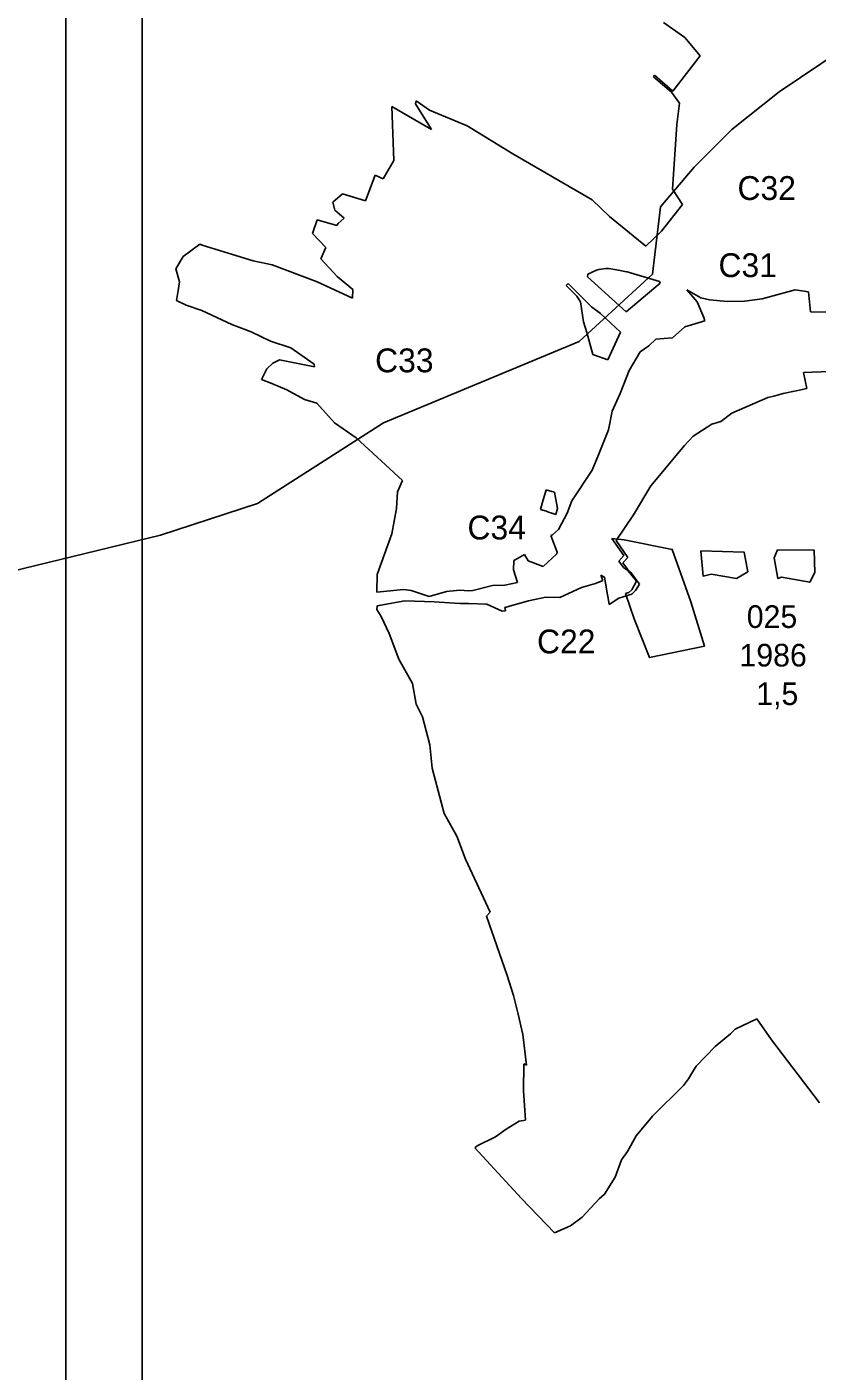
# Model space of a CAD drawing. Extents: x -557103 to -548162, y -1041918 to -1033974.
# Drawn here: x -555357 to -554362, y -1039045 to -1037353 of the extents above; entities that cross this region are included whole.
import ezdxf

# ---------------------------------------------------------------- set-up
doc = ezdxf.new("R2010")
doc.units = 0
for name, color, linetype in [('body1', 7, 'Continuous'), ('body3', 7, 'Continuous'), ('Rámeček', 7, 'Continuous'), ('Vrstva 16', 7, 'Continuous'), ('Vrstva 37', 7, 'Continuous'), ('Vrstva 9', 7, 'Continuous')]:
    doc.layers.add(name, color=color, linetype=linetype)

msp = doc.modelspace()

# ---------------------------------------------------------------- linework, layer by layer
at = {"layer": 'body1'}
msp.add_lwpolyline([(-550469.3, -1040018.6), (-555211.6, -1040018.6), (-555211.6, -1034654.7), (-550469.3, -1034654.7)], close=True, dxfattribs=at)
at = {"layer": 'body3'}
for p, q in [((-554555.1, -1037348), (-554528.3, -1037366.9)), ((-554528.3, -1037366.9), (-554509.2, -1037390)), ((-554509.2, -1037390), (-554543.6, -1037434.2)), ((-554566.4, -1037414.3), (-554567.7, -1037416.2)), ((-554543.6, -1037434.2), (-554566.4, -1037414.3)), ((-554567.7, -1037416.2), (-554545, -1037435.7)), ((-554866.5, -1037446.5), (-554867.6, -1037450.3)), ((-554849.7, -1037458.1), (-554866.5, -1037446.5)), ((-554545, -1037435.7), (-554534.9, -1037449.4)), ((-554847.4, -1037482.8), (-554897.1, -1037453.8)), ((-554897.1, -1037453.8), (-554894.8, -1037521.6)), ((-554867.6, -1037450.3), (-554847.4, -1037482.8)), ((-554802.2, -1037478), (-554849.7, -1037458.1)), ((-554534.9, -1037449.4), (-554538.3, -1037476.5)), ((-554744.8, -1037513.3), (-554802.2, -1037478)), ((-554538.3, -1037476.5), (-554544, -1037557.7)), ((-554644.8, -1037571.1), (-554744.8, -1037513.3)), ((-554894.8, -1037521.6), (-554908.1, -1037544.8)), ((-554918.2, -1037539.9), (-554930.4, -1037572.5)), ((-554908.1, -1037544.8), (-554918.2, -1037539.9)), ((-554959.2, -1037563.4), (-554971.7, -1037573.9)), ((-554930.4, -1037572.5), (-554959.2, -1037563.4)), ((-554544, -1037557.7), (-554531.3, -1037576.9)), ((-554971.7, -1037573.9), (-554968.9, -1037584.2)), ((-554968.9, -1037584.2), (-554957.3, -1037594)), ((-554623.2, -1037591.9), (-554644.8, -1037571.1)), ((-554531.3, -1037576.9), (-554557.8, -1037610.7)), ((-554991.2, -1037596.1), (-554997.1, -1037613.4)), ((-554966.6, -1037603.5), (-554991.2, -1037596.1)), ((-554965, -1037600.9), (-554966.6, -1037603.5)), ((-554957.3, -1037594), (-554965, -1037600.9)), ((-554577.2, -1037629.5), (-554623.2, -1037591.9)), ((-554997.1, -1037613.4), (-554980.4, -1037631.2)), ((-554557.8, -1037610.7), (-554577.2, -1037629.5)), ((-555139.1, -1037627), (-555160, -1037642.6)), ((-555135.9, -1037628.2), (-555139.1, -1037627)), ((-555097.7, -1037639.9), (-555135.9, -1037628.2)), ((-554980.4, -1037631.2), (-554986.6, -1037645.4)), ((-555160, -1037642.6), (-555169.1, -1037658.1)), ((-555071.7, -1037647.8), (-555097.7, -1037639.9)), ((-555048, -1037652.9), (-555071.7, -1037647.8)), ((-554986.6, -1037645.4), (-554965.9, -1037667.7)), ((-555169.1, -1037658.1), (-555164.8, -1037674.5)), ((-554991.4, -1037674.5), (-555048, -1037652.9)), ((-554965.9, -1037667.7), (-554946.2, -1037684.1)), ((-554650.8, -1037668), (-554650.3, -1037664.8)), ((-554602.3, -1037712.2), (-554650.8, -1037668)), ((-554650.3, -1037664.8), (-554639.5, -1037659.6)), ((-554639.5, -1037659.6), (-554636.6, -1037658.8)), ((-554636.6, -1037658.8), (-554630.6, -1037658)), ((-554630.6, -1037658), (-554627.6, -1037657.7)), ((-554627.6, -1037657.7), (-554624.6, -1037657.7)), ((-554624.6, -1037657.7), (-554621.6, -1037658)), ((-554621.6, -1037658), (-554609.9, -1037660)), ((-554609.9, -1037660), (-554604, -1037661.2)), ((-554604, -1037661.2), (-554601.1, -1037661.9)), ((-554601.1, -1037661.9), (-554560.2, -1037673.8)), ((-555166.5, -1037685.3), (-555168.5, -1037697.7)), ((-555164.8, -1037674.5), (-555166.5, -1037685.3)), ((-554946.7, -1037695), (-554991.4, -1037674.5)), ((-554946.2, -1037684.1), (-554946.7, -1037695)), ((-554677.7, -1037679.1), (-554675.1, -1037676.6)), ((-554664.3, -1037692.3), (-554677.7, -1037679.1)), ((-554675.1, -1037676.6), (-554645.9, -1037705.7)), ((-554559.4, -1037676), (-554602.3, -1037712.2)), ((-554560.2, -1037673.8), (-554559.4, -1037676)), ((-554512.9, -1037699.5), (-554525.9, -1037684.5)), ((-554525.9, -1037684.5), (-554508, -1037694.3)), ((-554430.8, -1037695.6), (-554389.5, -1037684.6)), ((-554389.5, -1037684.6), (-554372.6, -1037686.9)), ((-555168.5, -1037697.7), (-555156.2, -1037703.5)), ((-554659.6, -1037699.7), (-554664.3, -1037692.3)), ((-554655.8, -1037724.7), (-554659.6, -1037699.7)), ((-554504.2, -1037719.4), (-554512.9, -1037699.5)), ((-554508, -1037694.3), (-554497.1, -1037697.1)), ((-554497.1, -1037697.1), (-554474.7, -1037698.9)), ((-554474.7, -1037698.9), (-554453.1, -1037698.6)), ((-554453.1, -1037698.6), (-554430.8, -1037695.6)), ((-554372.6, -1037686.9), (-554370.2, -1037712)), ((-555156.2, -1037703.5), (-555136.7, -1037710.3)), ((-555136.7, -1037710.3), (-555098.7, -1037728.2)), ((-554645.9, -1037705.7), (-554634.3, -1037714.3)), ((-554634.3, -1037714.3), (-554609.3, -1037737.7)), ((-554503.1, -1037723.3), (-554504.2, -1037719.4)), ((-554370.2, -1037712), (-554337.8, -1037712.6)), ((-555098.7, -1037728.2), (-555074.2, -1037737.2)), ((-554651.9, -1037738.1), (-554655.8, -1037724.7)), ((-554543.7, -1037744.9), (-554528.2, -1037731)), ((-554528.2, -1037731), (-554503.1, -1037723.3)), ((-555074.2, -1037737.2), (-555049.9, -1037749)), ((-555049.9, -1037749), (-555024.6, -1037757.5)), ((-554644.1, -1037765.9), (-554651.9, -1037738.1)), ((-554609.3, -1037737.7), (-554625.3, -1037772.6)), ((-554573.6, -1037754.8), (-554564.8, -1037746.7)), ((-554564.8, -1037746.7), (-554543.7, -1037744.9)), ((-555024.6, -1037757.5), (-554995, -1037777.8)), ((-554625.3, -1037772.6), (-554644.1, -1037765.9)), ((-554598.4, -1037785.9), (-554584.7, -1037762.4)), ((-554584.7, -1037762.4), (-554573.6, -1037754.8)), ((-555054.8, -1037784), (-555061.2, -1037797.1)), ((-555047.3, -1037776.8), (-555054.8, -1037784)), ((-555038.9, -1037772.7), (-555047.3, -1037776.8)), ((-554994.8, -1037781.5), (-555038.9, -1037772.7)), ((-554995, -1037777.8), (-554994.8, -1037781.5)), ((-554609.6, -1037814.8), (-554598.4, -1037785.9)), ((-554304.4, -1037785.4), (-554378.9, -1037788.6)), ((-555061.2, -1037797.1), (-555048.4, -1037802.2)), ((-555048.4, -1037802.2), (-555029.6, -1037810.2)), ((-554378.9, -1037788.6), (-554374.6, -1037808.6)), ((-555029.6, -1037810.2), (-555007.4, -1037822.3)), ((-554619.8, -1037837.3), (-554609.6, -1037814.8)), ((-554423.7, -1037820), (-554469.3, -1037839.7)), ((-554416.4, -1037818.2), (-554423.7, -1037820)), ((-554404.3, -1037814.7), (-554416.4, -1037818.2)), ((-554388, -1037811.4), (-554404.3, -1037814.7)), ((-554374.6, -1037808.6), (-554388, -1037811.4)), ((-555007.4, -1037822.3), (-554991.6, -1037827.2)), ((-554991.6, -1037827.2), (-554969.3, -1037851.7)), ((-554624.6, -1037860.5), (-554619.8, -1037837.3)), ((-554969.3, -1037851.7), (-554942.1, -1037870.8)), ((-554494.1, -1037853.3), (-554517.6, -1037868.8)), ((-554482.9, -1037850.1), (-554494.1, -1037853.3)), ((-554469.3, -1037839.7), (-554482.9, -1037850.1)), ((-554942.1, -1037870.8), (-554884, -1037924.3)), ((-554637.2, -1037892.1), (-554624.6, -1037860.5)), ((-554517.6, -1037868.8), (-554528.7, -1037880.3)), ((-554528.7, -1037880.3), (-554571.2, -1037931.2)), ((-554644.8, -1037911.5), (-554637.2, -1037892.1)), ((-554670.6, -1037950.1), (-554644.8, -1037911.5)), ((-554890.2, -1037938.6), (-554891.4, -1037959.7)), ((-554884, -1037924.3), (-554890.2, -1037938.6)), ((-554707.5, -1037951.8), (-554702.7, -1037936.1)), ((-554702.7, -1037936.1), (-554695.8, -1037938.3)), ((-554695.8, -1037938.3), (-554692.4, -1037939.2)), ((-554692.4, -1037939.2), (-554688.5, -1037959.8)), ((-554571.2, -1037931.2), (-554593, -1037967.8)), ((-554710.2, -1037960.8), (-554707.5, -1037951.8)), ((-554676.6, -1037965.6), (-554670.6, -1037950.1)), ((-554891.4, -1037959.7), (-554897.3, -1037991.4)), ((-554702.6, -1037963.2), (-554710.2, -1037960.8)), ((-554700, -1037964.1), (-554702.6, -1037963.2)), ((-554697.1, -1037965), (-554700, -1037964.1)), ((-554690.8, -1037967), (-554697.1, -1037965)), ((-554688.5, -1037959.8), (-554690.8, -1037967)), ((-554687.3, -1037986.2), (-554676.6, -1037965.6)), ((-554593, -1037967.8), (-554614.9, -1038000)), ((-554695.1, -1037992.7), (-554687.3, -1037986.2)), ((-554897.3, -1037991.4), (-554915.7, -1038042.6)), ((-554696.9, -1037993.8), (-554695.1, -1037992.7)), ((-554688.9, -1038014.6), (-554696.9, -1037993.8)), ((-554614.9, -1038000), (-554599.9, -1038021.3)), ((-554743.6, -1038025.1), (-554741.9, -1038024.1)), ((-554741.9, -1038024.1), (-554730.1, -1038017.5)), ((-554730.1, -1038017.5), (-554725.6, -1038025.6)), ((-554706.8, -1038032.8), (-554689.3, -1038016.6)), ((-554689.3, -1038016.6), (-554688.9, -1038014.6)), ((-554599.9, -1038021.3), (-554606.3, -1038028.1)), ((-554744.2, -1038036.9), (-554743.6, -1038025.1)), ((-554739, -1038052.6), (-554744.2, -1038036.9)), ((-554725.6, -1038025.6), (-554706.8, -1038032.8)), ((-554606.3, -1038028.1), (-554600.7, -1038036.2)), ((-554600.7, -1038036.2), (-554596.2, -1038040)), ((-554596.2, -1038040), (-554594.6, -1038042.1)), ((-554915.7, -1038042.6), (-554916.3, -1038065.1)), ((-554795.4, -1038062.8), (-554770.6, -1038056.5)), ((-554770.6, -1038056.5), (-554754.9, -1038056.3)), ((-554754.9, -1038056.3), (-554739, -1038052.6)), ((-554640.6, -1038053.9), (-554658.5, -1038059.1)), ((-554631.6, -1038050.2), (-554640.6, -1038053.9)), ((-554629.4, -1038045.9), (-554634, -1038043.7)), ((-554634, -1038043.7), (-554631.6, -1038050.2)), ((-554627.4, -1038058.3), (-554629.4, -1038045.9)), ((-554594.6, -1038042.1), (-554589.1, -1038049.7)), ((-554585.3, -1038054.8), (-554590.3, -1038062.8)), ((-554589.1, -1038049.7), (-554585.3, -1038054.8)), ((-554916.3, -1038065.1), (-554882.6, -1038061.4)), ((-554882.6, -1038061.4), (-554873.1, -1038062.8)), ((-554873.1, -1038062.8), (-554850.2, -1038070.5)), ((-554850.2, -1038070.5), (-554828.3, -1038064.3)), ((-554828.3, -1038064.3), (-554811.7, -1038062.4)), ((-554811.7, -1038062.4), (-554800.8, -1038063.2)), ((-554800.8, -1038063.2), (-554795.4, -1038062.8)), ((-554703.4, -1038071.1), (-554725.1, -1038076)), ((-554685.7, -1038071.8), (-554703.4, -1038071.1)), ((-554658.5, -1038059.1), (-554685.7, -1038071.8)), ((-554626.4, -1038063.7), (-554627.4, -1038058.3)), ((-554624.6, -1038075.1), (-554626.4, -1038063.7)), ((-554611.6, -1038072.3), (-554623.7, -1038080.3)), ((-554595, -1038067.6), (-554611.6, -1038072.3)), ((-554590.3, -1038062.8), (-554595, -1038067.6)), ((-554915.7, -1038082.3), (-554916.3, -1038086.7)), ((-554916.3, -1038086.7), (-554910.5, -1038095.6)), ((-554880.8, -1038075.8), (-554915.7, -1038082.3)), ((-554843.8, -1038077), (-554880.8, -1038075.8)), ((-554811.6, -1038079), (-554843.8, -1038077)), ((-554806.4, -1038079.2), (-554811.6, -1038079)), ((-554800.5, -1038079.4), (-554806.4, -1038079.2)), ((-554777.6, -1038080.2), (-554800.5, -1038079.4)), ((-554758.4, -1038089), (-554777.6, -1038080.2)), ((-554754.2, -1038088.3), (-554758.4, -1038089)), ((-554725.1, -1038076), (-554755, -1038084.3)), ((-554755, -1038084.3), (-554754.2, -1038088.3)), ((-554623.7, -1038080.3), (-554624.6, -1038075.1)), ((-554910.5, -1038095.6), (-554900.7, -1038117.1)), ((-554900.7, -1038117.1), (-554888.6, -1038149.1)), ((-554888.6, -1038149.1), (-554871.2, -1038179.8)), ((-554871.2, -1038179.8), (-554866.4, -1038206)), ((-554866.4, -1038206), (-554858.5, -1038221.9)), ((-554858.5, -1038221.9), (-554849.5, -1038257)), ((-554849.5, -1038257), (-554846.3, -1038286.5)), ((-554846.3, -1038286.5), (-554831.2, -1038343.4)), ((-554831.2, -1038343.4), (-554815.2, -1038371.9)), ((-554815.2, -1038371.9), (-554804.6, -1038401.1)), ((-554804.6, -1038401.1), (-554773.3, -1038467.9)), ((-554773.3, -1038467.9), (-554778.1, -1038472.8)), ((-554778.1, -1038472.8), (-554752.2, -1038547.4)), ((-554752.2, -1038547.4), (-554744.2, -1038572.4)), ((-554744.2, -1038572.4), (-554738.1, -1038595.9)), ((-554738.1, -1038595.9), (-554732.1, -1038621.7)), ((-554471, -1038620.8), (-554464.8, -1038615.1)), ((-554464.8, -1038615.1), (-554437.8, -1038602)), ((-554437.8, -1038602), (-554419.3, -1038628.4)), ((-554732.1, -1038621.7), (-554727.7, -1038660.3)), ((-554489.9, -1038636.9), (-554471, -1038620.8)), ((-554419.3, -1038628.4), (-554358.8, -1038707.9)), ((-554514.1, -1038661.6), (-554489.9, -1038636.9)), ((-554731.1, -1038658.8), (-554731.5, -1038692.4)), ((-554727.7, -1038660.3), (-554731.1, -1038658.8)), ((-554520.8, -1038672.6), (-554514.1, -1038661.6)), ((-554529.8, -1038685.8), (-554523.8, -1038677.6)), ((-554523.8, -1038677.6), (-554520.8, -1038672.6)), ((-554731.5, -1038692.4), (-554728.9, -1038729.5)), ((-554569.2, -1038724.6), (-554529.8, -1038685.8)), ((-554736.7, -1038730.9), (-554753.4, -1038740.8)), ((-554728.9, -1038729.5), (-554736.7, -1038730.9)), ((-554589.6, -1038749.4), (-554569.2, -1038724.6)), ((-554766.8, -1038750.5), (-554789.8, -1038762)), ((-554753.4, -1038740.8), (-554766.8, -1038750.5)), ((-554600.6, -1038768.9), (-554589.6, -1038749.4)), ((-554789.8, -1038762), (-554792.9, -1038764.4)), ((-554792.9, -1038764.4), (-554733.8, -1038828.1)), ((-554616, -1038801.2), (-554608.2, -1038779.5)), ((-554608.2, -1038779.5), (-554600.6, -1038768.9)), ((-554629.6, -1038822.5), (-554616, -1038801.2)), ((-554733.8, -1038828.1), (-554692.4, -1038871.2)), ((-554657.4, -1038851.4), (-554636.1, -1038828.4)), ((-554636.1, -1038828.4), (-554629.6, -1038822.5)), ((-554672.3, -1038862.7), (-554657.4, -1038851.4)), ((-554692.4, -1038871.2), (-554672.3, -1038862.7))]:
    msp.add_line(p, q, dxfattribs=at)
at = {"layer": 'Rámeček'}
for points in [[(-555307.9, -1039662.1), (-550042, -1039662.1), (-550042, -1034604.4), (-555307.9, -1034604.4)], [(-555307.9, -1034604.4), (-548161.9, -1034604.4), (-548161.9, -1039661.8), (-555307.9, -1039661.8)]]:
    msp.add_lwpolyline(points, close=True, dxfattribs=at)
at = {"layer": 'Vrstva 16'}
msp.add_lwpolyline([(-554172.9, -1037275.9), (-554409.6, -1037435.4), (-554469.3, -1037482.8), (-554516.7, -1037530.1), (-554559, -1037580), (-554569, -1037664.7), (-554661.2, -1037749.5), (-554907.8, -1037851.7), (-555066.3, -1037953.4), (-555188.4, -1037993.2), (-555425.1, -1038050.6)], dxfattribs=at)
at = {"layer": 'Vrstva 9'}
msp.add_line((-554604.8, -1037999.2), (-554620.2, -1037997.6), dxfattribs=at)
msp.add_lwpolyline([(-554620.2, -1037997.6), (-554605.2, -1038019), (-554611.2, -1038026.1), (-554605.5, -1038033.9), (-554600.2, -1038037.5), (-554589.2, -1038051.1), (-554595.1, -1038061.9), (-554598.7, -1038065.4), (-554603, -1038066.8), (-554591.9, -1038098.6), (-554572.6, -1038147.3), (-554503.6, -1038133.1), (-554520.6, -1038076.9), (-554544.1, -1038011.1), (-554604.8, -1037999.2)], dxfattribs=at)
for points in [[(-554508.2, -1038013), (-554453.5, -1038014.8), (-554448.9, -1038039.2), (-554463.1, -1038047.9), (-554495.3, -1038042.4), (-554505.4, -1038044.7)], [(-554411.6, -1038011.6), (-554365.6, -1038012), (-554364.7, -1038040.1), (-554371.1, -1038052.5), (-554406.5, -1038046.1), (-554411.1, -1038047.9), (-554415.7, -1038021.7)]]:
    msp.add_lwpolyline(points, close=True, dxfattribs=at)

# ---------------------------------------------------------------- texts
at = {"layer": 'Vrstva 37'}
for s, p in [('C32', (-554462, -1037571.3)), ('C31', (-554485.9, -1037668.4)), ('C33', (-554918.3, -1037788.2)), ('C34', (-554802, -1037998.6)), ('C22', (-554714.4, -1038142))]:
    msp.add_text(s, height=30, dxfattribs=at).set_placement(p)
at = {"layer": 'Vrstva 9'}
for s, p in [('025', (-554450.3, -1038110)), ('1986', (-554459.5, -1038158.5)), ('1,5', (-554438.4, -1038207))]:
    msp.add_text(s, height=28.5, dxfattribs=at).set_placement(p)

doc.saveas('drawing.dxf')
